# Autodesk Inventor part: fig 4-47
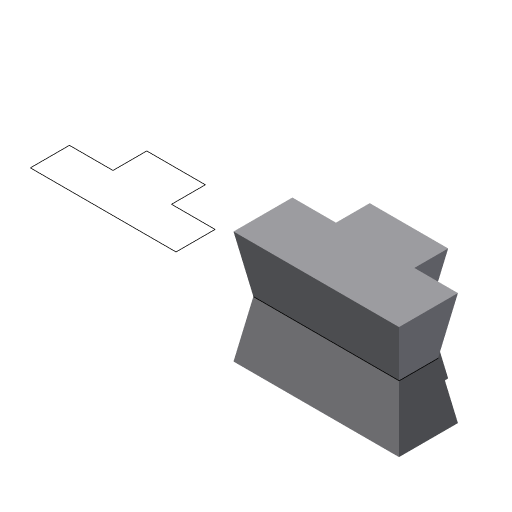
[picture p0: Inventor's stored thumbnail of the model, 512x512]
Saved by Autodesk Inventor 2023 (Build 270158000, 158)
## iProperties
Created: 2004-05
Part Number: fig 4-47
Document SubType Name: Modeling
Designer: CADCIM Technologies
Manufacturer: Standard
Standards Organization: Custom
Density: 1 g/cm^3
Material: Generic
Appearance: Default
Author: CADCIM Technologies
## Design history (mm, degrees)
sketch "Sketch1"
  geometry: L1 (31.783, 34.561)-(31.783, 22.933); L2 (31.783, 22.933)-(16.796, 22.933); L3 (16.796, 22.933)-(16.796, 9.496); L4 (16.796, 9.496)-(66.925, 9.496); L5 (66.925, 9.496)-(66.925, 22.933); L6 (66.925, 22.933)-(51.938, 22.933); L7 (51.938, 22.933)-(51.938, 34.561); L8 (51.938, 34.561)-(31.783, 34.561); L9 (-45.013, 34.561)-(-45.013, 22.933); L10 (-45.013, 22.933)-(-60, 22.933); L11 (-60, 22.933)-(-60, 9.496); L12 (-60, 9.496)-(-9.871, 9.496); L13 (-9.871, 9.496)-(-9.871, 22.933); L14 (-9.871, 22.933)-(-24.858, 22.933); L15 (-24.858, 22.933)-(-24.858, 34.561); L16 (-24.858, 34.561)-(-45.013, 34.561)
  constraints: 32 end point, 10 parallel, 4 equal length, 2 collinear, 2 perpendicular, 2 vertical
extrude "Extrusion2" new body sketch "Sketch1" stored distance "d2" = 38.75; taper "d3" = 10 deg
body "Solid2"
